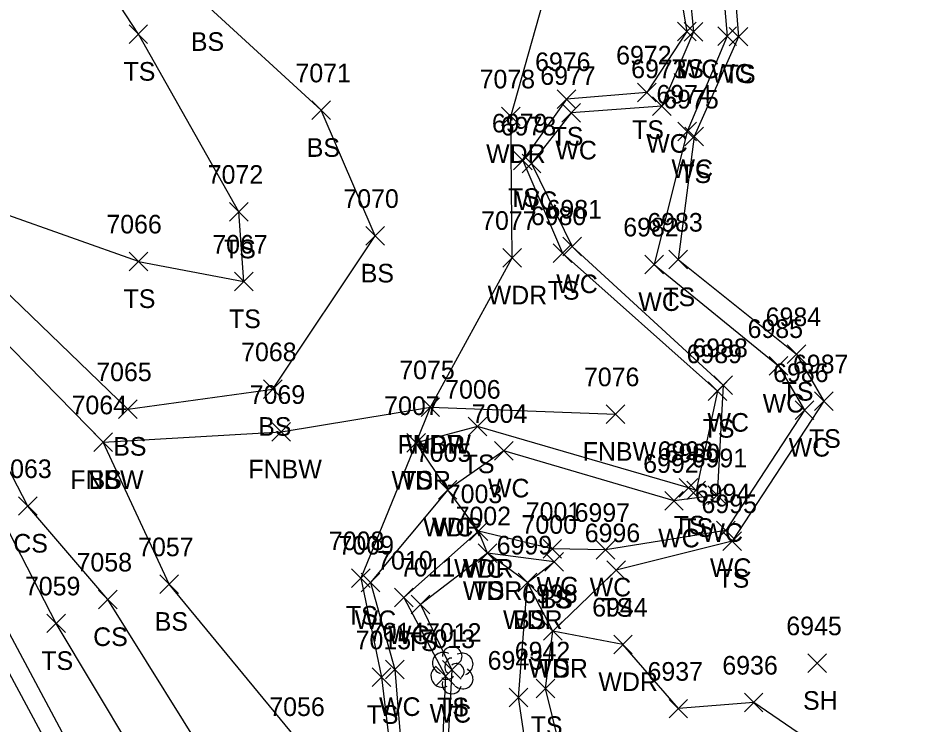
# Model space of a CAD drawing. Extents: x 1439173 to 1457902, y 641926 to 659889.
# Drawn here: x 1448822.7 to 1448918.5, y 643870.3 to 643946.2 of the extents above; entities that cross this region are included whole.
import ezdxf

# ---------------------------------------------------------------- set-up
doc = ezdxf.new("R2010")
doc.units = 0
for name, color, linetype in [('L_A', 7, 'Continuous'), ('L_I', 7, 'Continuous'), ('L_TIC', 7, 'Continuous'), ('LAWA', 7, 'Continuous'), ('LAWE', 7, 'Continuous'), ('LELB', 7, 'Continuous'), ('LFNC', 7, 'Continuous'), ('LTD', 7, 'Continuous'), ('PET', 7, 'Continuous'), ('PSP', 7, 'Continuous')]:
    doc.layers.add(name, color=color, linetype=linetype)

msp = doc.modelspace()

# ---------------------------------------------------------------- linework, layer by layer
at = {"layer": 'L_TIC'}
for points in [[(1448893.517, 643943.703), (1448895.517, 643945.703)], [(1448895.517, 643943.703), (1448893.517, 643945.703)], [(1448834.659, 643943.41), (1448836.659, 643945.41)], [(1448836.659, 643943.41), (1448834.659, 643945.41)], [(1448894.227, 643943.667), (1448896.227, 643945.667)], [(1448896.227, 643943.667), (1448894.227, 643945.667)], [(1448897.829, 643943.198), (1448899.829, 643945.198)], [(1448899.829, 643943.198), (1448897.829, 643945.198)], [(1448899.073, 643943.135), (1448901.073, 643945.135)], [(1448901.073, 643943.135), (1448899.073, 643945.135)], [(1448889.235, 643937.152), (1448891.235, 643939.152)], [(1448891.235, 643937.152), (1448889.235, 643939.152)], [(1448880.593, 643936.44), (1448882.593, 643938.44)], [(1448882.593, 643936.44), (1448880.593, 643938.44)], [(1448854.292, 643935.235), (1448856.292, 643937.235)], [(1448856.292, 643935.235), (1448854.292, 643937.235)], [(1448890.847, 643935.679), (1448892.847, 643937.679)], [(1448892.847, 643935.679), (1448890.847, 643937.679)], [(1448874.617, 643934.584), (1448876.617, 643936.584)], [(1448876.617, 643934.584), (1448874.617, 643936.584)], [(1448881.098, 643934.959), (1448883.098, 643936.959)], [(1448883.098, 643934.959), (1448881.098, 643936.959)], [(1448893.56, 643932.953), (1448895.56, 643934.953)], [(1448895.56, 643932.953), (1448893.56, 643934.953)], [(1448894.299, 643932.424), (1448896.299, 643934.424)], [(1448896.299, 643932.424), (1448894.299, 643934.424)], [(1448875.91, 643929.855), (1448877.91, 643931.855)], [(1448877.91, 643929.855), (1448875.91, 643931.855)], [(1448876.852, 643929.533), (1448878.852, 643931.533)], [(1448878.852, 643929.533), (1448876.852, 643931.533)], [(1448845.443, 643924.344), (1448847.443, 643926.344)], [(1448847.443, 643924.344), (1448845.443, 643926.344)], [(1448860.083, 643921.754), (1448862.083, 643923.754)], [(1448862.083, 643921.754), (1448860.083, 643923.754)], [(1448880.168, 643919.906), (1448882.168, 643921.906)], [(1448882.168, 643919.906), (1448880.168, 643921.906)], [(1448881.199, 643920.61), (1448883.199, 643922.61)], [(1448883.199, 643920.61), (1448881.199, 643922.61)], [(1448834.666, 643919.012), (1448836.666, 643921.012)], [(1448836.666, 643919.012), (1448834.666, 643921.012)], [(1448834.666, 643919.012), (1448836.666, 643921.012)], [(1448836.666, 643919.012), (1448834.666, 643921.012)], [(1448874.78, 643919.399), (1448876.78, 643921.399)], [(1448876.78, 643919.399), (1448874.78, 643921.399)], [(1448892.581, 643919.209), (1448894.581, 643921.209)], [(1448894.581, 643919.209), (1448892.581, 643921.209)], [(1448890.003, 643918.696), (1448892.003, 643920.696)], [(1448892.003, 643918.696), (1448890.003, 643920.696)], [(1448845.976, 643916.853), (1448847.976, 643918.853)], [(1448847.976, 643916.853), (1448845.976, 643918.853)], [(1448905.28, 643909.066), (1448907.28, 643911.066)], [(1448907.28, 643909.066), (1448905.28, 643911.066)], [(1448903.343, 643907.794), (1448905.343, 643909.794)], [(1448905.343, 643907.794), (1448903.343, 643909.794)], [(1448897.417, 643905.734), (1448899.417, 643907.734)], [(1448899.417, 643905.734), (1448897.417, 643907.734)], [(1448849.074, 643905.298), (1448851.074, 643907.298)], [(1448851.074, 643905.298), (1448849.074, 643907.298)], [(1448896.804, 643905.09), (1448898.804, 643907.09)], [(1448898.804, 643905.09), (1448896.804, 643907.09)], [(1448908.209, 643904.002), (1448910.209, 643906.002)], [(1448910.209, 643904.002), (1448908.209, 643906.002)], [(1448833.527, 643903.16), (1448835.527, 643905.16)], [(1448835.527, 643903.16), (1448833.527, 643905.16)], [(1448833.527, 643903.16), (1448835.527, 643905.16)], [(1448835.527, 643903.16), (1448833.527, 643905.16)], [(1448865.992, 643903.367), (1448867.992, 643905.367)], [(1448867.992, 643903.367), (1448865.992, 643905.367)], [(1448865.992, 643903.367), (1448867.992, 643905.367)], [(1448867.992, 643903.367), (1448865.992, 643905.367)], [(1448885.866, 643902.613), (1448887.866, 643904.613)], [(1448887.866, 643902.613), (1448885.866, 643904.613)], [(1448906.136, 643903.061), (1448908.136, 643905.061)], [(1448908.136, 643903.061), (1448906.136, 643905.061)], [(1448850, 643900.719), (1448852, 643902.719)], [(1448852, 643900.719), (1448850, 643902.719)], [(1448871.06, 643901.279), (1448873.06, 643903.279)], [(1448873.06, 643901.279), (1448871.06, 643903.279)], [(1448830.879, 643899.602), (1448832.879, 643901.602)], [(1448832.879, 643899.602), (1448830.879, 643901.602)], [(1448830.879, 643899.602), (1448832.879, 643901.602)], [(1448832.879, 643899.602), (1448830.879, 643901.602)], [(1448864.458, 643899.525), (1448866.458, 643901.525)], [(1448866.458, 643899.525), (1448864.458, 643901.525)], [(1448864.458, 643899.525), (1448866.458, 643901.525)], [(1448866.458, 643899.525), (1448864.458, 643901.525)], [(1448873.867, 643898.684), (1448875.867, 643900.684)], [(1448875.867, 643898.684), (1448873.867, 643900.684)], [(1448867.851, 643894.5), (1448869.851, 643896.5)], [(1448869.851, 643894.5), (1448867.851, 643896.5)], [(1448867.851, 643894.5), (1448869.851, 643896.5)], [(1448869.851, 643894.5), (1448867.851, 643896.5)], [(1448893.691, 643894.701), (1448895.691, 643896.701)], [(1448895.691, 643894.701), (1448893.691, 643896.701)], [(1448894.524, 643894.44), (1448896.524, 643896.44)], [(1448896.524, 643894.44), (1448894.524, 643896.44)], [(1448896.776, 643893.911), (1448898.776, 643895.911)], [(1448898.776, 643893.911), (1448896.776, 643895.911)], [(1448892.138, 643893.32), (1448894.138, 643895.32)], [(1448894.138, 643893.32), (1448892.138, 643895.32)], [(1448822.799, 643892.759), (1448824.799, 643894.759)], [(1448824.799, 643892.759), (1448822.799, 643894.759)], [(1448871.177, 643890.063), (1448873.177, 643892.063)], [(1448873.177, 643890.063), (1448871.177, 643892.063)], [(1448871.177, 643890.063), (1448873.177, 643892.063)], [(1448873.177, 643890.063), (1448871.177, 643892.063)], [(1448897.687, 643890.142), (1448899.687, 643892.142)], [(1448899.687, 643890.142), (1448897.687, 643892.142)], [(1448879.082, 643888.155), (1448881.082, 643890.155)], [(1448881.082, 643888.155), (1448879.082, 643890.155)], [(1448898.394, 643888.994), (1448900.394, 643890.994)], [(1448900.394, 643888.994), (1448898.394, 643890.994)], [(1448872.118, 643887.685), (1448874.118, 643889.685)], [(1448874.118, 643887.685), (1448872.118, 643889.685)], [(1448872.118, 643887.685), (1448874.118, 643889.685)], [(1448874.118, 643887.685), (1448872.118, 643889.685)], [(1448884.778, 643888.057), (1448886.778, 643890.057)], [(1448886.778, 643888.057), (1448884.778, 643890.057)], [(1448879.281, 643886.778), (1448881.281, 643888.778)], [(1448881.281, 643886.778), (1448879.281, 643888.778)], [(1448879.281, 643886.778), (1448881.281, 643888.778)], [(1448881.281, 643886.778), (1448879.281, 643888.778)], [(1448885.921, 643885.872), (1448887.921, 643887.872)], [(1448887.921, 643885.872), (1448885.921, 643887.872)], [(1448837.975, 643884.367), (1448839.975, 643886.367)], [(1448839.975, 643884.367), (1448837.975, 643886.367)], [(1448858.522, 643885.022), (1448860.522, 643887.022)], [(1448860.522, 643885.022), (1448858.522, 643887.022)], [(1448859.566, 643884.551), (1448861.566, 643886.551)], [(1448861.566, 643884.551), (1448859.566, 643886.551)], [(1448876.428, 643884.559), (1448878.428, 643886.559)], [(1448878.428, 643884.559), (1448876.428, 643886.559)], [(1448876.428, 643884.559), (1448878.428, 643886.559)], [(1448878.428, 643884.559), (1448876.428, 643886.559)], [(1448831.37, 643882.731), (1448833.37, 643884.731)], [(1448833.37, 643882.731), (1448831.37, 643884.731)], [(1448863.144, 643882.933), (1448865.144, 643884.933)], [(1448865.144, 643882.933), (1448863.144, 643884.933)], [(1448864.932, 643882.192), (1448866.932, 643884.192)], [(1448866.932, 643882.192), (1448864.932, 643884.192)], [(1448825.836, 643880.165), (1448827.836, 643882.165)], [(1448827.836, 643880.165), (1448825.836, 643882.165)], [(1448879.145, 643879.342), (1448881.145, 643881.342)], [(1448881.145, 643879.342), (1448879.145, 643881.342)], [(1448879.145, 643879.342), (1448881.145, 643881.342)], [(1448881.145, 643879.342), (1448879.145, 643881.342)], [(1448879.145, 643879.342), (1448881.145, 643881.342)], [(1448881.145, 643879.342), (1448879.145, 643881.342)], [(1448886.665, 643877.897), (1448888.665, 643879.897)], [(1448888.665, 643877.897), (1448886.665, 643879.897)], [(1448907.498, 643875.888), (1448909.498, 643877.888)], [(1448909.498, 643875.888), (1448907.498, 643877.888)], [(1448862.178, 643875.224), (1448864.178, 643877.224)], [(1448864.178, 643875.224), (1448862.178, 643877.224)], [(1448868.298, 643875.183), (1448870.298, 643877.183)], [(1448870.298, 643875.183), (1448868.298, 643877.183)], [(1448860.744, 643874.38), (1448862.744, 643876.38)], [(1448862.744, 643874.38), (1448860.744, 643876.38)], [(1448867.613, 643874.506), (1448869.613, 643876.506)], [(1448869.613, 643874.506), (1448867.613, 643876.506)], [(1448878.359, 643873.185), (1448880.359, 643875.185)], [(1448880.359, 643873.185), (1448878.359, 643875.185)], [(1448875.453, 643872.193), (1448877.453, 643874.193)], [(1448877.453, 643872.193), (1448875.453, 643874.193)], [(1448892.603, 643871.007), (1448894.603, 643873.007)], [(1448894.603, 643871.007), (1448892.603, 643873.007)], [(1448900.687, 643871.662), (1448902.687, 643873.662)], [(1448902.687, 643871.662), (1448900.687, 643873.662)]]:
    msp.add_lwpolyline(points, dxfattribs=at)
at = {"layer": 'LAWA'}
msp.add_lwpolyline([(1448935.189, 643849.955), (1448930.895, 643850.557), (1448912.473, 643865.306), (1448901.687, 643872.662), (1448893.603, 643872.007), (1448887.665, 643878.897), (1448880.145, 643880.342), (1448877.428, 643885.559), (1448873.118, 643888.685), (1448872.177, 643891.063), (1448868.851, 643895.5), (1448865.458, 643900.525), (1448866.992, 643904.367), (1448875.78, 643920.399), (1448875.617, 643935.584), (1448881.787, 643957.412), (1448868.1, 643977.702), (1448859.214, 644002.854), (1448858.885, 644027.761), (1448856.912, 644066.774)], dxfattribs=at)
at = {"layer": 'LAWE'}
for points in [[(1448895.935, 643978.844), (1448893.673, 643960.994), (1448895.227, 643944.667), (1448891.847, 643936.679), (1448882.098, 643935.959), (1448877.852, 643930.533), (1448882.199, 643921.61), (1448898.417, 643906.734), (1448897.776, 643894.911), (1448893.138, 643894.32), (1448874.867, 643899.684), (1448868.851, 643895.5), (1448860.566, 643885.551), (1448863.178, 643876.224), (1448864.951, 643854.692), (1448862.827, 643842.39)], [(1448899.566, 643975.944), (1448897.371, 643961.171), (1448898.829, 643944.198), (1448894.56, 643933.953), (1448891.003, 643919.696), (1448904.343, 643908.794), (1448907.136, 643904.061), (1448898.687, 643891.142), (1448885.778, 643889.057), (1448880.082, 643889.155), (1448872.177, 643891.063), (1448864.144, 643883.933), (1448868.613, 643875.506), (1448867.659, 643854.09), (1448866.738, 643846.284), (1448867.001, 643839.972), (1448873.308, 643828.828), (1448871.354, 643828), (1448871.404, 643829.12), (1448865.117, 643829.65), (1448862.984, 643832.525), (1448866.15, 643838.134), (1448865.28, 643838.744), (1448862.827, 643842.39)]]:
    msp.add_lwpolyline(points, dxfattribs=at)
at = {"layer": 'LELB'}
for points in [[(1448835.666, 643920.012), (1448813.845, 643927.741), (1448807.246, 643938.49), (1448787.504, 643971.177), (1448769.798, 644005.906), (1448753.68, 644037.514), (1448732.595, 644075.616), (1448723.349, 644091.128), (1448721.471, 644097.938), (1448722.859, 644102.828), (1448722.465, 644106.414), (1448715.935, 644111.565), (1448711.756, 644124.49), (1448703.646, 644145.793), (1448694.937, 644171.311), (1448678.242, 644218.21), (1448664.751, 644266.637), (1448650.893, 644312.746), (1448655.721, 644319.77), (1448674.905, 644329.67), (1448705.255, 644337.733), (1448737.049, 644346.611), (1448757.707, 644352.713)], [(1448865.271, 643838.341), (1448861.657, 643841.903), (1448853.107, 643868.218), (1448838.975, 643885.367), (1448831.879, 643900.602), (1448813.991, 643918.86), (1448801.93, 643933.534), (1448782.168, 643967.389), (1448763.235, 644002.706), (1448747.337, 644033.172), (1448728.734, 644074.308), (1448718.9, 644096.065), (1448715.672, 644106.806), (1448706.694, 644124.251), (1448699.652, 644145.033), (1448688.952, 644169.075), (1448674.332, 644217.193), (1448660.897, 644265.469), (1448648.106, 644311.856), (1448650.049, 644334.081), (1448650.168, 644347.104)], [(1448834.527, 643904.16), (1448812.746, 643925.138), (1448803.6, 643934.015), (1448784.064, 643968.445), (1448765.024, 644003.714), (1448748.863, 644033.971), (1448728.817, 644074.947), (1448718.9, 644096.065), (1448718.301, 644106.562), (1448707.412, 644124.444), (1448701.492, 644146.419), (1448691.886, 644170.182), (1448675.904, 644217.749), (1448662.6, 644266.07), (1448648.106, 644311.856)], [(1448835.666, 643920.012), (1448846.976, 643917.853), (1448846.443, 643925.344), (1448835.659, 643944.41), (1448816.561, 643973.56), (1448814.573, 643993.491), (1448811.82, 644020.304), (1448797.587, 644030.965), (1448785.954, 644053.764), (1448769.817, 644086.666), (1448752.068, 644086.668), (1448737.256, 644085.664), (1448728.157, 644089.816), (1448725.716, 644098.089), (1448722.859, 644102.828)], [(1448834.527, 643904.16), (1448850.074, 643906.298), (1448861.083, 643922.754), (1448855.292, 643936.235), (1448842.855, 643947.609), (1448836.174, 643982.004), (1448829.582, 644004.818), (1448828.914, 644021.782), (1448812.503, 644040.65), (1448802.343, 644060.44), (1448797.522, 644079.312), (1448788.638, 644092.517), (1448771.826, 644100.841)], [(1448909.197, 643729.39), (1448906.116, 643729.98), (1448902.734, 643732.59), (1448891.538, 643753.399), (1448885.605, 643768.019), (1448878.521, 643783.538), (1448870.378, 643798.091), (1448862.58, 643811.811), (1448854.276, 643826.812), (1448838.963, 643860.888), (1448826.836, 643881.165), (1448819.944, 643894.502), (1448797.652, 643933.24), (1448780.238, 643967.088), (1448761.694, 644002.145), (1448746.211, 644032.5), (1448726.199, 644073.88)], [(1448895.034, 643979.773), (1448891.657, 643961.352), (1448894.517, 643944.703), (1448890.235, 643938.152), (1448881.593, 643937.44), (1448876.91, 643930.855), (1448881.168, 643920.906), (1448897.804, 643906.09), (1448895.524, 643895.44), (1448894.691, 643895.701), (1448872.06, 643902.279), (1448865.458, 643900.525), (1448859.522, 643886.022), (1448861.744, 643875.38), (1448864.241, 643854.533), (1448861.657, 643841.903)], [(1448900.302, 643975.15), (1448898.71, 643961.083), (1448900.073, 643944.135), (1448895.299, 643933.424), (1448893.581, 643920.209), (1448906.28, 643910.066), (1448909.209, 643905.002), (1448899.394, 643889.994), (1448886.921, 643886.872), (1448880.145, 643880.342)], [(1448878.521, 643783.538), (1448875.387, 643800.827), (1448864.362, 643827.978), (1448861.81, 643832.758), (1448857.534, 643839.263), (1448844.64, 643864.042), (1448832.37, 643883.731), (1448823.799, 643893.759), (1448811.394, 643917.726), (1448801.93, 643933.534)], [(1448880.281, 643887.778), (1448873.118, 643888.685), (1448865.932, 643883.192), (1448869.298, 643876.183), (1448867.644, 643845.761), (1448868.122, 643840.129), (1448873.308, 643828.828)], [(1448905.092, 643733.215), (1448906.974, 643730.807), (1448908.131, 643731.204), (1448906.193, 643734.411), (1448895.749, 643755.884), (1448892.962, 643769.945), (1448887.765, 643800.921), (1448885.641, 643819.169), (1448893.676, 643829.162), (1448894.449, 643833.22), (1448892.201, 643837.365), (1448884.102, 643842.019), (1448882.434, 643835.273), (1448877.693, 643835.652), (1448876.059, 643854.096), (1448884.608, 643849.666), (1448903.911, 643861.643), (1448886.483, 643858.598), (1448878.127, 643861.993), (1448876.453, 643873.193), (1448877.428, 643885.559), (1448880.281, 643887.778)], [(1448903.911, 643861.643), (1448884.905, 643861.926), (1448881.631, 643864.904), (1448879.359, 643874.185), (1448880.145, 643880.342)]]:
    msp.add_lwpolyline(points, dxfattribs=at)
at = {"layer": 'LFNC'}
msp.add_lwpolyline([(1448831.879, 643900.602), (1448851, 643901.719), (1448866.992, 643904.367), (1448886.866, 643903.613)], dxfattribs=at)
at = {"layer": 'LTD'}
msp.add_line((1448869.298, 643876.183), (1448869.298, 643876.183), dxfattribs=at)
msp.add_line((1448869.298, 643876.183), (1448869.298, 643876.183), dxfattribs=at)
msp.add_arc((1448869.345, 643877.617), 1.047, 335.52715, 180.95627, dxfattribs=at)
for centre, major_axis, ratio, start_param, end_param in [((1448868.506, 643876.849), (1.21, -0.512), 0.895232, 1.570796, 4.712389), ((1448870.34, 643876.766), (-1.141, -0.483), 0.949671, 1.570796, 4.712389), ((1448869.09, 643876.641), (-0.208, -0.792), 0.645439, 3.141593, 6.283185), ((1448869.798, 643876.016), (-0.5, 0.667), 0.989748, 3.141593, 6.283185), ((1448868.215, 643875.474), (0.584, -1.042), 0.959034, 3.141593, 6.283185), ((1448870.298, 643875.35), (-1.09, 0.792), 0.841452, 1.570796, 4.712389), ((1448869.298, 643874.683), (0.265, 1.061), 0.942809, 1.570796, 4.712389), ((1448868.84, 643875.433), (-0.625, -0.083), 0.423636, 0, 3.141593)]:
    msp.add_ellipse(centre, major_axis=major_axis, ratio=ratio, start_param=start_param, end_param=end_param, dxfattribs=at)
at = {"layer": 'PET'}
msp.add_lwpolyline([(1449162.581, 643198.272), (1449141.478, 643242.395), (1449121.689, 643284.019), (1449089.798, 643350.471), (1449063.608, 643404.763), (1449045.086, 643442.414), (1449024.862, 643484.454), (1449010.101, 643514.114), (1448990.81, 643553.035), (1448970.838, 643592.715), (1448947.224, 643637.956), (1448929.605, 643671.834), (1448913.026, 643703.205), (1448880.265, 643765.401), (1448860.142, 643803.648), (1448849.295, 643824.32), (1448831.931, 643856.996), (1448813.546, 643891.177), (1448792.864, 643930.507), (1448774.914, 643964.184), (1448756.706, 643999.716), (1448741.681, 644029.904), (1448721.663, 644072.108)], dxfattribs=at)
at = {"layer": 'PSP'}
msp.add_lwpolyline([(1448977.119, 643597.858), (1448952.223, 643640.32), (1448934.182, 643673.754), (1448916.627, 643701.762), (1448901.189, 643730.961), (1448882.071, 643766.446), (1448862.012, 643805.036), (1448851.258, 643825.513), (1448833.678, 643857.893), (1448815.319, 643892.207), (1448795.505, 643930.366), (1448776.764, 643965.35), (1448758.73, 644000.568), (1448743.185, 644030.791), (1448723.718, 644072.962)], dxfattribs=at)

# ---------------------------------------------------------------- texts
at = {"layer": 'L_A'}
for s, p in [('BS', (1448841.296, 643942.609)), ('TS', (1448834.069, 643939.41)), ('TS', (1448892.927, 643939.703)), ('WC', (1448893.534, 643939.667)), ('WC', (1448897.136, 643939.198)), ('TS', (1448898.483, 643939.135)), ('TS', (1448888.644, 643933.152)), ('TS', (1448880.003, 643932.44)), ('BS', (1448853.733, 643931.235)), ('WC', (1448890.154, 643931.679)), ('WDR', (1448872.979, 643930.584)), ('WC', (1448880.405, 643930.959)), ('WC', (1448892.867, 643928.953)), ('TS', (1448893.709, 643928.424)), ('TS', (1448875.319, 643925.855)), ('WC', (1448876.159, 643925.533)), ('TS', (1448844.852, 643920.344)), ('BS', (1448859.524, 643917.754)), ('TS', (1448879.577, 643915.906)), ('WC', (1448880.506, 643916.61)), ('TS', (1448834.075, 643915.012)), ('TS', (1448834.075, 643915.012)), ('WDR', (1448873.142, 643915.399)), ('TS', (1448891.99, 643915.209)), ('WC', (1448889.31, 643914.696)), ('TS', (1448845.385, 643912.853)), ('TS', (1448904.689, 643905.066)), ('WC', (1448902.65, 643903.794)), ('WC', (1448896.724, 643901.734)), ('BS', (1448848.515, 643901.298)), ('TS', (1448896.214, 643901.09)), ('TS', (1448907.618, 643900.002)), ('BS', (1448832.968, 643899.16)), ('BS', (1448832.968, 643899.16)), ('FNBW', (1448863.465, 643899.367)), ('WDR', (1448864.354, 643899.367)), ('WC', (1448905.443, 643899.061)), ('FNBW', (1448883.339, 643898.613)), ('TS', (1448870.469, 643897.279)), ('FNBW', (1448847.473, 643896.719)), ('FNBW', (1448828.352, 643895.602)), ('BS', (1448830.32, 643895.602)), ('WDR', (1448862.821, 643895.525)), ('TS', (1448863.868, 643895.525)), ('WC', (1448873.174, 643894.684)), ('WDR', (1448866.213, 643890.5)), ('WC', (1448867.158, 643890.5)), ('TS', (1448893.1, 643890.701)), ('TS', (1448893.933, 643890.44)), ('WC', (1448891.445, 643889.32)), ('WC', (1448896.083, 643889.911)), ('CS', (1448822.24, 643888.759)), ('WDR', (1448869.539, 643886.063)), ('WC', (1448870.484, 643886.063)), ('WC', (1448896.994, 643886.142)), ('TS', (1448897.804, 643884.994)), ('WDR', (1448870.48, 643883.685)), ('TS', (1448871.527, 643883.685)), ('WC', (1448878.389, 643884.155)), ('WC', (1448884.085, 643884.057)), ('TS', (1448878.69, 643882.778)), ('BS', (1448878.722, 643882.778)), ('TS', (1448885.331, 643881.872)), ('TS', (1448857.931, 643881.022)), ('WC', (1448858.873, 643880.551)), ('WDR', (1448874.79, 643880.559)), ('BS', (1448875.869, 643880.559)), ('BS', (1448837.416, 643880.367)), ('CS', (1448830.811, 643878.731)), ('WC', (1448862.451, 643878.933)), ('TS', (1448864.342, 643878.192)), ('TS', (1448825.246, 643876.165)), ('WDR', (1448877.508, 643875.342)), ('TS', (1448878.555, 643875.342)), ('TS', (1448878.555, 643875.342)), ('WDR', (1448885.027, 643873.897)), ('SH', (1448906.986, 643871.888)), ('WC', (1448861.485, 643871.224)), ('TS', (1448867.708, 643871.183)), ('H', (1448868.731, 643871.183)), ('TS', (1448860.153, 643870.38)), ('WC', (1448866.92, 643870.506)), ('TS', (1448877.768, 643869.185))]:
    msp.add_text(s, height=2, dxfattribs=at).set_placement(p)
at = {"layer": 'L_I'}
for s, p in [('6972', (1448886.928, 643941.152)), ('6976', (1448878.231, 643940.44)), ('7071', (1448852.52, 643939.235)), ('6977', (1448878.791, 643938.959)), ('6973', (1448888.54, 643939.679)), ('7078', (1448872.279, 643938.584)), ('6974', (1448891.253, 643936.953)), ('6975', (1448891.992, 643936.424)), ('6979', (1448873.595, 643933.855)), ('6978', (1448874.545, 643933.533)), ('7072', (1448843.104, 643928.344)), ('7070', (1448857.658, 643925.754)), ('6981', (1448879.459, 643924.61)), ('6980', (1448877.774, 643923.906)), ('7066', (1448832.225, 643923.012)), ('7066', (1448832.225, 643923.012)), ('7077', (1448872.442, 643923.399)), ('6982', (1448887.696, 643922.696)), ('6983', (1448890.274, 643923.209)), ('7067', (1448843.59, 643920.853)), ('6984', (1448902.973, 643913.066)), ('6985', (1448901.036, 643911.794)), ('7068', (1448846.688, 643909.298)), ('6988', (1448895.11, 643909.734)), ('6989', (1448894.489, 643909.09)), ('7075', (1448863.654, 643907.367)), ('7075', (1448863.654, 643907.367)), ('6987', (1448905.902, 643908.002)), ('7065', (1448831.141, 643907.16)), ('7065', (1448831.141, 643907.16)), ('7076', (1448883.473, 643906.613)), ('6986', (1448903.773, 643907.061)), ('7069', (1448847.607, 643904.719)), ('7006', (1448868.587, 643905.279)), ('7064', (1448828.493, 643903.602)), ('7064', (1448828.493, 643903.602)), ('7007', (1448862.041, 643903.525)), ('7007', (1448862.041, 643903.525)), ('7004', (1448871.45, 643902.684)), ('6993', (1448891.384, 643898.701)), ('7005', (1448865.433, 643898.5)), ('7005', (1448865.433, 643898.5)), ('6990', (1448892.13, 643898.44)), ('6991', (1448895.036, 643897.911)), ('7063', (1448820.413, 643896.759)), ('6992', (1448889.831, 643897.32)), ('7003', (1448868.759, 643894.063)), ('7003', (1448868.759, 643894.063)), ('6994', (1448895.379, 643894.142)), ('6995', (1448896.087, 643892.994)), ('7001', (1448877.231, 643892.155)), ('6997', (1448882.471, 643892.057)), ('7002', (1448869.7, 643891.685)), ('7002', (1448869.7, 643891.685)), ('7000', (1448876.777, 643890.778)), ('7000', (1448876.777, 643890.778)), ('6996', (1448883.559, 643889.872)), ('7057', (1448835.636, 643888.367)), ('7008', (1448856.105, 643889.022)), ('7009', (1448857.141, 643888.551)), ('6999', (1448874.113, 643888.559)), ('6999', (1448874.113, 643888.559)), ('7058', (1448829.031, 643886.731)), ('7010', (1448861.286, 643886.933)), ('7011', (1448863.727, 643886.192)), ('7059', (1448823.49, 643884.165)), ('6998', (1448876.838, 643883.342)), ('6998', (1448876.838, 643883.342)), ('6998', (1448876.838, 643883.342)), ('6944', (1448884.358, 643881.897)), ('6945', (1448905.191, 643879.888)), ('7014', (1448860.406, 643879.224)), ('7012', (1448866.526, 643879.183)), ('7012', (1448866.526, 643879.183)), ('7015', (1448858.972, 643878.38)), ('7013', (1448865.841, 643878.506)), ('6942', (1448876.052, 643877.185)), ('6943', (1448873.145, 643876.193)), ('6936', (1448898.325, 643875.662)), ('6937', (1448890.296, 643875.007)), ('7056', (1448849.713, 643871.218))]:
    msp.add_text(s, height=2, dxfattribs=at).set_placement(p)

doc.saveas('drawing.dxf')
